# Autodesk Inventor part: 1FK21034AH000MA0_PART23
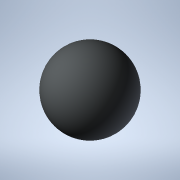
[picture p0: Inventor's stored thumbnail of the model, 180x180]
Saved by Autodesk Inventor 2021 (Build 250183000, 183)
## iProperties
Created: 2025-04
Part Number: 1FK21034AH000MA0_PART23
Material: Generic
Catalog Web Link: www.3dfindit.com
Description: -Servo synchronous motor
Document SubType Name: Modeling
Designer: psAdmin
Mass: 0.113097 g
Surface Area: 1.13097 cm^2
Volume: 0.113097 cm^3
Density: 1 g/cm^3
Appearance: PSOLRGB-212-217-219
Category: PARTsolutions
Title: 1FK21034AH000MA0_PART23
Author: Cadenas PARTsolutions
Comments: Servo synchronous motor
Sending System: PARTsolutions
Preprocessor: ST-DEVELOPER v19.3
PSOL_IDENT_0: {$CADENAS_DATA/23d-libs/siemens_ag/_cat_/ec/b7/1fk21034ah000ma0.prj},216 {VTYP=3D},{NB=1FK21034AH000
PSOL_IDENT_1: MA0_PART23},{LINA=1FK21034AH000MA0_PART23},{NN=1FK21034AH000MA0_PART23},{NOPRJ=TRUE},{DATE=19.08.202
PSOL_IDENT_2: 5 14:01:05},{GEOMDATE=30.07.2025 02:01:02},{VERSION=},{LINEID=10},{WBVAR=},{WBNUMERIC=}  {NB=1FK2103
PSOL_IDENT_3: 4AH000MA0_PART23},{LINA=1FK21034AH000MA0_PART23},{KT=DUMMY},{PREVIEW=../../../_pool_/7c/50/p_d211_xx
PSOL_IDENT_4: _00932j.png},{DESCSHORT=SIMOTICS S-1FK2 HD, SINAMICS S210 3AC 400V-480V, 1.01 Nm, 4500 rpm},{DESCLON
PSOL_IDENT_5: G=SIMOTICS S-1FK2 HD servo motor M0=1.27 Nm; PN = 0.48 kW at nN=4500 rpm (380-480 V); PN = 0.3 kW at
PSOL_IDENT_6: nN=2500 rpm (200-240 V); degree of protection IP64; cylindrical shaft D14 x 30 mm; absolute encoder
PSOL_IDENT_7: 22-bit + 12-bit multiturn (encoder AM22DQC); with OCC interface; plug size M17, rotatable; SIMOTICS
PSOL_IDENT_8: S-1FK2 servomotorfor a wide range of uses in industrial environments. SIMOTICS S‑1FK2 servomotors a
PSOL_IDENT_9: re compact synchronous motors with a high dynamic performance that set themselves apart as a result
PSOL_IDENT_10: of their high power density, degree of protection and overload capability. The motors are available
PSOL_IDENT_11: in two variants: as High Dynamic variant (highest dynamic performance as a result of the low intrins
PSOL_IDENT_12: ic moment of inertia for applications demanding a high dynamic performance with low moved masses) -
PSOL_IDENT_13: and as Compact variant (precise and stable closed-loop control for medium up to large moved masses a
PSOL_IDENT_14: s a result of a medium intrinsic moment of inertia). SIMOTICSS‑1FK2 servomotors fully exploit their
PSOL_IDENT_15: strengths in a system with the SINAMICSS210 frequency converter and simple connection using the one
PSOL_IDENT_16: cable connection (OCC). Advantages include the short control and positioning times, fast and precise
PSOL_IDENT_17: correction of disturbing quantities as well as stable control with a high dynamic performance. The
PSOL_IDENT_18: servo motors can be configured to address a wide range of requirements. For example with and without
PSOL_IDENT_19: holding brake, IP64 or IP65 degree of protection, singleturn or multiturn absolute encoders - to na
PSOL_IDENT_20: me just a few. Further, the servomotors are available in different shaft heights extending from 20 t
PSOL_IDENT_21: o 100. A shaft sealing ring is available to achieve an IP65 degree of protection and for subsequent
PSOL_IDENT_22: mounting at the motor or as spare part. SIMOTICS - the optimum motor for each and every motion contr
PSOL_IDENT_23: ol application.},{INTNO=4034106444822},{SUPPLIERALTNO=1FK2103-4AH00-0MA0},{MANUID=1FK21034AH000MA0},
PSOL_IDENT_24: {MANUNAME=Siemens},{MANUTYPEDESC=SYNCHRONOUS MOTOR 1FK2 HD 1,27 NM},{AAU732=SIMOTICS},{AAO057=S-1FK2
PSOL_IDENT_25: },{AAU734=SIMOTICS S-1FK2 HD servo motor M0=1.27 Nm; PN = 0.48 kW at nN=4500 rpm (380-480 V); PN = 0
PSOL_IDENT_26: .3 kW at nN=2500 rpm (200-240 V); degree of protection IP64; cylindrical shaft D14 x 30 mm; absolute
PSOL_IDENT_27: encoder 22-bit + 12-bit multiturn (encoder AM22DQC); with OCC interface; plug size M17, rotatable;}
PSOL_IDENT_28: ,{AAW338=SYNCHRONOUS MOTOR 1FK2 HD 1,27 NM},{AAO742=SIMOTICS},{AAO663=4034106444822},{NOCUPEROU=1},{
PSOL_IDENT_29: PRICEQUANTITY=1},{QUANTITYMIN=1},{QUANTITYINT=1},{CTN=85015100},{COO=RO},{AAO676=1FK2103-4AH00-0MA0}
PSOL_IDENT_30: ,{AAO677=Siemens AG},{ORDERUNIT=C62},{CONTENTUNIT=C62}
NB: 1FK21034AH000MA0_PART23
NT: Servo synchronous motor
NBSYN: $MANUID._PART23
LINA: 1FK21034AH000MA0_PART23
CATALOG: SIEMENS
PREVIEW: ../../../_pool_/7c/50/p_d211_xx_00932j.png
DESCSHORT: SIMOTICS S-1FK2 HD, SINAMICS S210 3AC 400V-480V, 1.01 Nm, 4500 rpm
DESCLONG: SIMOTICS S-1FK2 HD servo motor M0=1.27 Nm; PN = 0.48 kW at nN=4500 rpm (380-480 V); PN = 0.3 kW at nN=2500 rpm (200-240 V); degree of protection IP64; cylindric
INTNO: 4034106444822
SUPPLIERALTNO: 1FK2103-4AH00-0MA0
MANUID: 1FK21034AH000MA0
MANUNAME: Siemens
MANUTYPEDESC: SYNCHRONOUS MOTOR 1FK2 HD 1,27 NM
AAU732: SIMOTICS
AAO057: S-1FK2
AAU734: SIMOTICS S-1FK2 HD servo motor M0=1.27 Nm; PN = 0.48 kW at nN=4500 rpm (380-480 V); PN = 0.3 kW at nN=2500 rpm (200-240 V); degree of protection IP64; cylindric
AAW338: SYNCHRONOUS MOTOR 1FK2 HD 1,27 NM
AAO742: SIMOTICS
AAO663: 4034106444822.0
NOCUPEROU: 1
PRICEQUANTITY: 1
QUANTITYMIN: 1
QUANTITYINT: 1
CTN: 85015100
COO: RO
ARTICLENO: 1FK21034AH000MA0_PART23
BOMINFO: 1FK21034AH000MA0_PART23
CREATOR: CADENAS GmbH
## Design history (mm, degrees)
feature "2025_04_17_15_01_37_0314"
body "Solid1"
